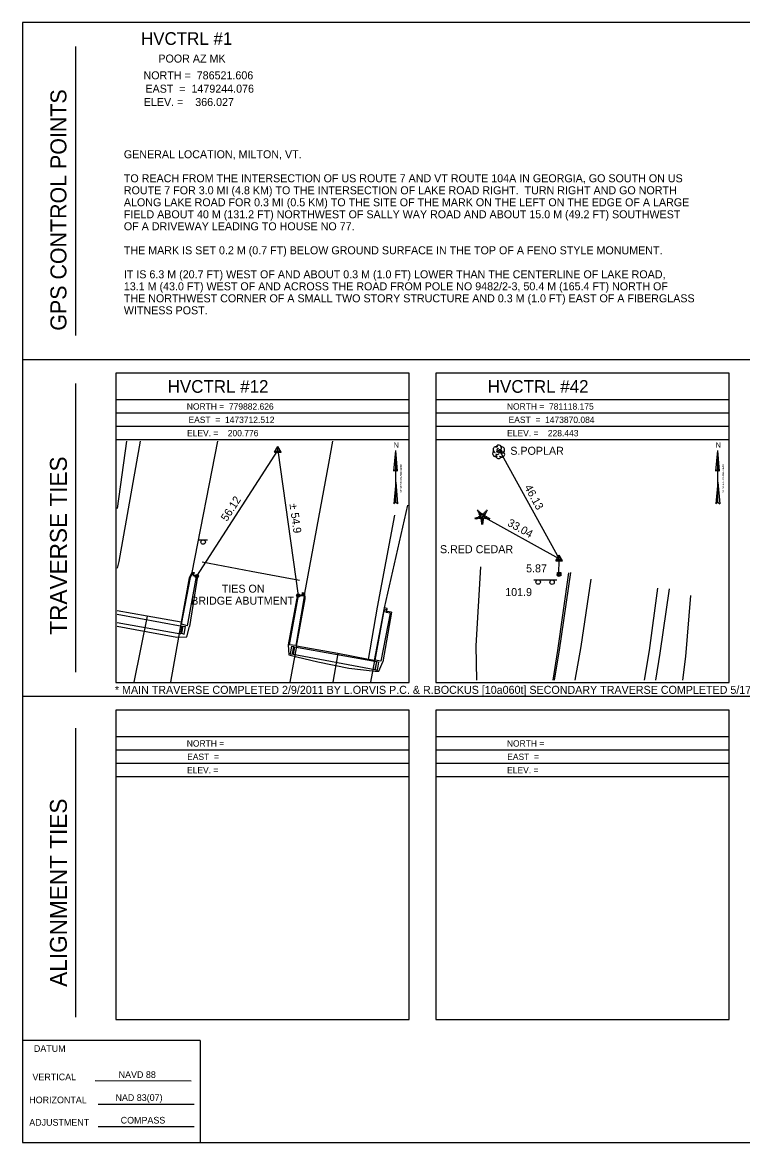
# Model space of a CAD drawing. Extents: x 1472556 to 1473196, y 780590 to 781010.
# Drawn here: x 1472555.8 to 1472825.8, y 780590.3 to 781010.3 of the extents above; entities that cross this region are included whole.
import ezdxf

# ---------------------------------------------------------------- set-up
doc = ezdxf.new("R2010")
doc.units = 0
for name, color, linetype in [('BELB', 7, 'Continuous'), ('BSE', 7, 'Continuous'), ('BSUBM', 7, 'Continuous'), ('CBP', 7, 'Continuous'), ('CPSM', 7, 'Continuous'), ('Default', 7, 'Continuous'), ('L_C', 7, 'Continuous'), ('LABL', 7, 'Continuous'), ('LARO', 7, 'Continuous'), ('LTC', 7, 'Continuous'), ('LTD', 7, 'Continuous'), ('NBL1', 7, 'Continuous'), ('NBL2', 7, 'Continuous'), ('NNA_P', 7, 'Continuous'), ('PET', 7, 'Continuous'), ('PSP', 7, 'Continuous'), ('RGR', 7, 'Continuous'), ('S_C', 7, 'Continuous'), ('SRM', 7, 'Continuous'), ('SSGN', 7, 'Continuous')]:
    doc.layers.add(name, color=color, linetype=linetype)

msp = doc.modelspace()

# ---------------------------------------------------------------- linework, layer by layer
at = {"layer": 'BELB'}
for points in [[(1472602.59, 780787.66), (1472597.5, 780762.96)], [(1472615.29, 780785.38), (1472611.28, 780762.96)], [(1472658.48, 780776.41), (1472656.01, 780762.96)], [(1472674.05, 780773.65), (1472672.15, 780762.96)], [(1472687.79, 780771.06), (1472686.28, 780762.96)]]:
    msp.add_lwpolyline(points, dxfattribs=at)
at = {"layer": 'BSE'}
for points in [[(1472591.36, 780788.41), (1472615.64, 780783.98)], [(1472591.36, 780785.36), (1472615.18, 780781.1), (1472615.64, 780783.98)], [(1472657.83, 780776.23), (1472657.33, 780773.41), (1472687.95, 780767.69)], [(1472657.83, 780776.23), (1472688.47, 780770.65), (1472687.95, 780767.69)]]:
    msp.add_lwpolyline(points, dxfattribs=at)
at = {"layer": 'BSUBM'}
for points in [[(1472617.66, 780784.06), (1472615.44, 780784.62), (1472618.76, 780802.17), (1472619.42, 780803.54), (1472619.92, 780803.51), (1472619.64, 780802.93), (1472621.02, 780802.58)], [(1472617.66, 780784.06), (1472621.02, 780802.58)], [(1472619.27, 780804.11), (1472620.11, 780804), (1472619.87, 780803.06), (1472621.41, 780802.68), (1472618.46, 780783.83)], [(1472658.92, 780795.76), (1472655.41, 780776.94), (1472655.6, 780773.22), (1472658.62, 780772.41), (1472666.5, 780770.53), (1472678.17, 780768.22), (1472688.03, 780767.04), (1472689.44, 780767.08), (1472690.9, 780770.6)], [(1472659.22, 780795.43), (1472661.11, 780795.31), (1472661.1, 780796.13), (1472661.54, 780796.12), (1472661.32, 780794.25), (1472658.24, 780776.71), (1472655.84, 780776.9)], [(1472659.22, 780795.43), (1472655.84, 780776.9)], [(1472658.92, 780795.76), (1472660.63, 780795.52), (1472660.78, 780796.61)], [(1472660.78, 780796.61), (1472661.69, 780796.3)], [(1472693.66, 780788.83), (1472690.19, 780770.82), (1472688.01, 780771.14), (1472691.3, 780789.11), (1472691.76, 780790.3), (1472692.11, 780790.19), (1472692.01, 780789.24), (1472693.67, 780788.9)], [(1472694.19, 780789.21), (1472690.9, 780770.6)], [(1472692.49, 780790.61), (1472691.48, 780790.77)], [(1472694.19, 780789.21), (1472692.42, 780789.48), (1472692.49, 780790.61)], [(1472693.66, 780788.83), (1472693.67, 780788.9)], [(1472591.36, 780783.93), (1472598.02, 780782.63), (1472613.68, 780779.87), (1472617.47, 780779.96), (1472618.46, 780783.83)], [(1472615.97, 780783.94), (1472615.39, 780781.28), (1472616.4, 780780.97), (1472616.88, 780783.77)], [(1472615.97, 780783.94), (1472616.88, 780783.77)], [(1472656.66, 780776.45), (1472656.14, 780773.6), (1472657.02, 780773.41), (1472657.51, 780776.31)], [(1472656.66, 780776.45), (1472657.51, 780776.31)], [(1472688.58, 780770.63), (1472688.08, 780767.67), (1472688.9, 780767.43), (1472689.44, 780770.44)], [(1472688.58, 780770.63), (1472689.44, 780770.44)]]:
    msp.add_lwpolyline(points, dxfattribs=at)
at = {"layer": 'CBP'}
for centre, radius in [((1472734.72, 780849.54), 0.625), ((1472734.72, 780849.54), 0.0833), ((1472728.11, 780825.22), 0.625), ((1472728.11, 780825.22), 0.0833), ((1472621.13, 780802.65), 0.625), ((1472621.13, 780802.65), 0.0833), ((1472756.88, 780803.24), 0.625), ((1472756.88, 780803.24), 0.0833), ((1472659.22, 780795.43), 0.625), ((1472659.22, 780795.43), 0.0833)]:
    msp.add_circle(centre, radius, dxfattribs=at)
at = {"layer": 'CPSM'}
for p, q in [((1472650.31, 780849.11), (1472651.56, 780851.27)), ((1472650.31, 780849.11), (1472651.57, 780849.83)), ((1472650.31, 780849.11), (1472652.81, 780849.11)), ((1472652.81, 780849.11), (1472651.56, 780851.27)), ((1472651.57, 780849.83), (1472651.56, 780851.27)), ((1472651.57, 780849.83), (1472651.57, 780849.83)), ((1472651.57, 780849.83), (1472652.81, 780849.11)), ((1472755.71, 780808.4), (1472756.96, 780810.56)), ((1472758.21, 780808.4), (1472756.96, 780810.56)), ((1472756.96, 780809.12), (1472756.96, 780810.56)), ((1472755.71, 780808.4), (1472756.96, 780809.12)), ((1472755.71, 780808.4), (1472758.21, 780808.4)), ((1472756.96, 780809.12), (1472756.96, 780809.12)), ((1472756.96, 780809.12), (1472758.21, 780808.4))]:
    msp.add_line(p, q, dxfattribs=at)
at = {"layer": 'Default'}
for p, q in [((1472621.13, 780802.65), (1472651.57, 780849.83)), ((1472651.57, 780849.83), (1472659.22, 780795.43)), ((1472734.72, 780849.54), (1472756.96, 780809.12)), ((1472756.96, 780809.12), (1472728.11, 780825.22)), ((1472756.88, 780803.24), (1472756.96, 780809.12))]:
    msp.add_line(p, q, dxfattribs=at)
at = {"layer": 'LABL'}
msp.add_lwpolyline([(1472727.55, 780806.14), (1472725.79, 780776.56), (1472725.97, 780763.69)], dxfattribs=at)
at = {"layer": 'LARO'}
msp.add_lwpolyline([(1472806.23, 780795.45), (1472804.41, 780772.54), (1472803.21, 780763.69)], dxfattribs=at)
at = {"layer": 'LTC'}
for p, q in [((1472726.32, 780827.25), (1472726.68, 780827.51)), ((1472726.53, 780826.79), (1472727.06, 780827.17)), ((1472726.74, 780826.32), (1472727.44, 780826.83)), ((1472726.95, 780825.85), (1472727.83, 780826.49)), ((1472728.61, 780826.45), (1472729.42, 780825.86)), ((1472728.98, 780826.8), (1472729.66, 780826.3)), ((1472729.35, 780827.14), (1472729.9, 780826.74)), ((1472729.72, 780827.49), (1472730.14, 780827.19)), ((1472725.35, 780824.53), (1472725.51, 780824.06)), ((1472725.81, 780824.75), (1472726.02, 780824.1)), ((1472726.26, 780824.96), (1472726.54, 780824.13)), ((1472726.72, 780825.18), (1472727.05, 780824.16)), ((1472727.17, 780825.4), (1472728.19, 780826.13)), ((1472727.17, 780825.4), (1472727.56, 780824.21)), ((1472728.79, 780824.21), (1472727.56, 780824.21)), ((1472728.75, 780823.71), (1472727.61, 780823.71)), ((1472728.67, 780823.21), (1472727.68, 780823.21)), ((1472728.59, 780822.71), (1472727.75, 780822.71)), ((1472728.5, 780822.21), (1472727.83, 780822.21)), ((1472728.19, 780826.13), (1472729.18, 780825.41)), ((1472729.18, 780825.41), (1472728.79, 780824.21)), ((1472729.62, 780825.14), (1472729.28, 780824.1)), ((1472730.07, 780824.89), (1472729.78, 780824)), ((1472730.51, 780824.64), (1472730.27, 780823.91)), ((1472730.95, 780824.39), (1472730.77, 780823.81))]:
    msp.add_line(p, q, dxfattribs=at)
at = {"layer": 'LTD'}
msp.add_line((1472734.31, 780849.36), (1472734.31, 780849.36), dxfattribs=at)
msp.add_line((1472734.31, 780849.36), (1472734.31, 780849.36), dxfattribs=at)
msp.add_arc((1472734.35, 780850.79), 1.05, 335.5272, 180.9563, dxfattribs=at)
for centre, major_axis, ratio, start_param, end_param in [((1472733.22, 780848.65), (0.58, -1.04), 0.959034, 3.141593, 6.283185), ((1472733.51, 780850.03), (1.21, -0.51), 0.895232, 1.570796, 4.712389), ((1472734.31, 780847.86), (0.26, 1.06), 0.942809, 1.570796, 4.712389), ((1472733.85, 780848.61), (-0.625, -0.083), 0.423636, 0, 3.141593), ((1472734.1, 780849.82), (-0.208, -0.792), 0.645439, 3.141593, 6.283185), ((1472734.81, 780849.19), (-0.5, 0.667), 0.989748, 3.141593, 6.283185), ((1472735.31, 780848.53), (-1.09, 0.79), 0.841452, 1.570796, 4.712389), ((1472735.35, 780849.94), (-1.14, -0.48), 0.949671, 1.570796, 4.712389)]:
    msp.add_ellipse(centre, major_axis=major_axis, ratio=ratio, start_param=start_param, end_param=end_param, dxfattribs=at)
at = {"layer": 'NBL1'}
msp.add_lwpolyline([(1472555.78, 780590.3), (1473195.78, 780590.3), (1473195.78, 781010.3), (1472555.78, 781010.3)], close=True, dxfattribs=at)
at = {"layer": 'NBL2'}
for p, q in [((1472575.78, 780892.97), (1472575.78, 781001.3)), ((1472555.78, 780883.97), (1473195.78, 780883.97)), ((1472575.78, 780766.64), (1472575.78, 780874.97)), ((1472700.78, 780868.8), (1472590.78, 780868.8)), ((1472820.78, 780868.8), (1472710.78, 780868.8)), ((1472700.78, 780863.8), (1472590.78, 780863.8)), ((1472820.78, 780863.8), (1472710.78, 780863.8)), ((1472700.78, 780858.8), (1472590.78, 780858.8)), ((1472820.78, 780858.8), (1472710.78, 780858.8)), ((1472700.78, 780853.8), (1472590.78, 780853.8)), ((1472820.78, 780853.8), (1472710.78, 780853.8)), ((1472555.78, 780757.64), (1473195.78, 780757.64)), ((1472575.78, 780637.3), (1472575.78, 780745.64)), ((1472700.78, 780742.47), (1472590.78, 780742.47)), ((1472820.78, 780742.47), (1472710.78, 780742.47)), ((1472700.78, 780737.47), (1472590.78, 780737.47)), ((1472820.78, 780737.47), (1472710.78, 780737.47)), ((1472700.78, 780732.47), (1472590.78, 780732.47)), ((1472820.78, 780732.47), (1472710.78, 780732.47)), ((1472700.78, 780727.47), (1472590.78, 780727.47)), ((1472820.78, 780727.47), (1472710.78, 780727.47)), ((1472622.44, 780628.56), (1472555.78, 780628.56)), ((1472622.44, 780628.56), (1472622.44, 780590.3)), ((1472622.44, 780628.56), (1472622.44, 780590.3)), ((1472583.02, 780613.53), (1472619.02, 780613.5)), ((1472584.13, 780604.76), (1472620.13, 780604.76)), ((1472584.13, 780596.32), (1472620.13, 780596.29))]:
    msp.add_line(p, q, dxfattribs=at)
for points in [[(1472590.78, 780762.8), (1472700.78, 780762.8), (1472700.78, 780878.8), (1472590.78, 780878.8)], [(1472710.78, 780762.8), (1472820.78, 780762.8), (1472820.78, 780878.8), (1472710.78, 780878.8)], [(1472590.78, 780636.47), (1472700.78, 780636.47), (1472700.78, 780752.47), (1472590.78, 780752.47)], [(1472710.78, 780636.47), (1472820.78, 780636.47), (1472820.78, 780752.47), (1472710.78, 780752.47)]]:
    msp.add_lwpolyline(points, close=True, dxfattribs=at)
at = {"layer": 'NNA_P'}
for p, q in [((1472695.02, 780842.02), (1472695.72, 780849.82)), ((1472695.72, 780830.44), (1472695.72, 780849.82)), ((1472696.41, 780842.02), (1472695.72, 780849.82)), ((1472815.78, 780842.02), (1472816.47, 780849.82)), ((1472816.48, 780830.44), (1472816.47, 780849.82)), ((1472817.17, 780842.02), (1472816.47, 780849.82)), ((1472695.02, 780842.02), (1472695.72, 780842.79)), ((1472696.41, 780842.02), (1472695.72, 780842.79)), ((1472815.78, 780842.02), (1472816.48, 780842.79)), ((1472817.17, 780842.02), (1472816.48, 780842.79)), ((1472695.72, 780837.97), (1472695, 780829.8)), ((1472695.72, 780837.97), (1472696.44, 780829.8)), ((1472816.48, 780837.97), (1472815.76, 780829.8)), ((1472816.48, 780837.97), (1472817.2, 780829.8)), ((1472695.72, 780830.44), (1472695, 780829.8)), ((1472695.72, 780830.44), (1472696.44, 780829.8)), ((1472816.48, 780830.44), (1472815.76, 780829.8)), ((1472816.48, 780830.44), (1472817.2, 780829.8))]:
    msp.add_line(p, q, dxfattribs=at)
at = {"layer": 'PET'}
for points in [[(1472628.9, 780853.32), (1472619.27, 780804.11), (1472618.34, 780802.08), (1472615.29, 780785.38), (1472602.59, 780787.66), (1472591.36, 780789.64)], [(1472599.97, 780853.32), (1472591.89, 780808.21), (1472591.36, 780805.69)], [(1472685.53, 780771.44), (1472674.05, 780773.65), (1472658.48, 780776.41), (1472661.73, 780794.17), (1472661.69, 780796.3), (1472670.7, 780844.92), (1472672.17, 780853.32)], [(1472687.79, 780771.06), (1472685.53, 780771.44), (1472688.89, 780791), (1472695.45, 780825.55)], [(1472768.91, 780801.5), (1472765.12, 780776.25), (1472762.92, 780763.69)], [(1472793.82, 780798.2), (1472790.77, 780774.86), (1472788.84, 780763.69)]]:
    msp.add_lwpolyline(points, dxfattribs=at)
at = {"layer": 'PSP'}
for points in [[(1472594.76, 780853.32), (1472591.36, 780828.06)], [(1472687.79, 780771.06), (1472691.48, 780790.77), (1472700.3, 780829.24)], [(1472761.21, 780804.04), (1472757, 780774.97), (1472755.11, 780763.69)], [(1472798.19, 780797.9), (1472794.74, 780773.87), (1472793.14, 780763.69)]]:
    msp.add_lwpolyline(points, dxfattribs=at)
at = {"layer": 'RGR'}
for points in [[(1472623.2, 780808.07), (1472641.56, 780804.59), (1472659.67, 780801.15)], [(1472760.54, 780803.97), (1472756.4, 780774.87), (1472754.58, 780763.69)]]:
    msp.add_lwpolyline(points, dxfattribs=at)
at = {"layer": 'SRM'}
msp.add_lwpolyline([(1472756.33, 780804.02), (1472757.58, 780804.02), (1472757.58, 780802.77), (1472756.33, 780802.77)], close=True, dxfattribs=at)
msp.add_circle((1472756.96, 780803.39), 0.0833, dxfattribs=at)
at = {"layer": 'SSGN'}
for p, q in [((1472621.89, 780816.31), (1472625.22, 780816.31)), ((1472623.53, 780815.47), (1472623.53, 780815.47)), ((1472747.48, 780801.31), (1472756.08, 780801.31)), ((1472751.5, 780800.41), (1472751.5, 780800.41))]:
    msp.add_line(p, q, dxfattribs=at)
for centre in [(1472623.53, 780815.47), (1472749.14, 780800.48), (1472754.36, 780800.41)]:
    msp.add_circle(centre, 0.833, dxfattribs=at)

# ---------------------------------------------------------------- texts
at = {"layer": 'Default'}
for s, p in [('GENERAL LOCATION, MILTON, VT.', (1472593.81, 780959.36)), ('TO REACH FROM THE INTERSECTION OF US ROUTE 7 AND VT ROUTE 104A IN GEORGIA, GO SOUTH ON US ', (1472593.81, 780950.36)), ('ROUTE 7 FOR 3.0 MI (4.8 KM) TO THE INTERSECTION OF LAKE ROAD RIGHT.  TURN RIGHT AND GO NORTH ', (1472593.81, 780945.86)), ('ALONG LAKE ROAD FOR 0.3 MI (0.5 KM) TO THE SITE OF THE MARK ON THE LEFT ON THE EDGE OF A LARGE ', (1472593.81, 780941.36)), ('FIELD ABOUT 40 M (131.2 FT) NORTHWEST OF SALLY WAY ROAD AND ABOUT 15.0 M (49.2 FT) SOUTHWEST ', (1472593.81, 780936.86)), ('OF A DRIVEWAY LEADING TO HOUSE NO 77.', (1472593.81, 780932.36)), ('THE MARK IS SET 0.2 M (0.7 FT) BELOW GROUND SURFACE IN THE TOP OF A FENO STYLE MONUMENT.', (1472593.81, 780923.36)), ('IT IS 6.3 M (20.7 FT) WEST OF AND ABOUT 0.3 M (1.0 FT) LOWER THAN THE CENTERLINE OF LAKE ROAD, ', (1472593.81, 780914.36)), ('13.1 M (43.0 FT) WEST OF AND ACROSS THE ROAD FROM POLE NO 9482/2-3, 50.4 M (165.4 FT) NORTH OF ', (1472593.81, 780909.86)), ('THE NORTHWEST CORNER OF A SMALL TWO STORY STRUCTURE AND 0.3 M (1.0 FT) EAST OF A FIBERGLASS ', (1472593.81, 780905.36)), ('WITNESS POST.', (1472593.81, 780900.86)), ('5.87', (1472744.61, 780804.11)), ('TIES ON', (1472630.51, 780796.49)), ('BRIDGE ABUTMENT', (1472619.05, 780791.99)), ('* MAIN TRAVERSE COMPLETED 2/9/2011 BY L.ORVIS P.C. & R.BOCKUS [10a060t] SECONDARY TRAVERSE COMPLETED 5/17/2011 BY L.ORVIS P.C. & G.HITCHCOCK ', (1472590.46, 780758.56))]:
    msp.add_text(s, height=3, dxfattribs=at).set_placement(p)
for s, rotation, p in [('46.13', 298.8129, (1472743.88, 780836)), ('56.12', 57.1768, (1472632.46, 780822.98)), ('±', 278.0089, (1472655.91, 780829.71)), (' 54.9', 278.0089, (1472656.23, 780827.43)), ('33.04', 330.8256, (1472737.34, 780821.79))]:
    msp.add_text(s, height=3, rotation=rotation, dxfattribs=at).set_placement(p)
at = {"layer": 'L_C'}
for s, p in [('S.POPLAR', (1472738.69, 780848.19)), ('S.RED CEDAR', (1472712.32, 780811.29))]:
    msp.add_text(s, height=3, dxfattribs=at).set_placement(p)
at = {"layer": 'LTC'}
msp.add_text('.', height=1.04, rotation=270, dxfattribs=at).set_placement((1472728.07, 780825.15))
at = {"layer": 'NBL2'}
for s, height, p in [('     HVCTRL #1     ', 4.75, (1472591.41, 781001.88)), ('     POOR AZ MK     ', 3, (1472601.18, 780995.25)), ('NORTH =  786521.606 ', 3, (1472601.18, 780988.96)), ('EAST  =  1479244.076', 3, (1472601.89, 780983.96)), ('ELEV. =    366.027  ', 3, (1472601.29, 780978.96)), ('     HVCTRL #12    ', 4.75, (1472601.42, 780871.43)), ('     HVCTRL #42    ', 4.75, (1472721.42, 780871.43)), ('NORTH =  779882.626 ', 2.375, (1472617.4, 780865.12)), ('NORTH =  781118.175 ', 2.375, (1472737.4, 780865.12)), ('EAST  =  1473712.512', 2.375, (1472618.05, 780860.12)), ('EAST  =  1473870.084', 2.375, (1472738.05, 780860.12)), ('ELEV. =    200.776  ', 2.375, (1472617.5, 780855.12)), ('ELEV. =    228.443  ', 2.375, (1472737.5, 780855.12)), ('NORTH =             ', 2.375, (1472617.4, 780738.78)), ('NORTH =             ', 2.375, (1472737.4, 780738.78)), ('EAST  =             ', 2.375, (1472617.54, 780733.78)), ('EAST  =             ', 2.375, (1472737.54, 780733.78)), ('ELEV. =             ', 2.375, (1472617.5, 780728.78)), ('ELEV. =             ', 2.375, (1472737.5, 780728.78)), ('DATUM', 2.5, (1472560.09, 780624.32)), ('  NAVD 88 ', 2.5, (1472590, 780614.54)), ('NAD 83(07) ', 2.5, (1472590.67, 780605.93)), ('HORIZONTAL', 2.5, (1472558.35, 780605.06)), ('  COMPASS ', 2.5, (1472590.77, 780597.45)), ('ADJUSTMENT', 2.5, (1472558.35, 780596.62))]:
    msp.add_text(s, height=height, dxfattribs=at).set_placement(p)
for s, height, rotation, p in [('GPS CONTROL POINTS', 6, 90, (1472572.28, 780894.72)), ('TRAVERSE TIES', 6.3332, 90, (1472572.44, 780780.74)), ('ALIGNMENT TIES', 6.3332, 90, (1472572.44, 780648.71)), ('VERTICAL', 2.5, 0.1439, (1472559.55, 780613.65))]:
    msp.add_text(s, height=height, rotation=rotation, dxfattribs=at).set_placement(p)
at = {"layer": 'NNA_P'}
for p in [(1472694.95, 780850.83), (1472815.71, 780850.83)]:
    msp.add_text('N', height=1.97, dxfattribs=at).set_placement(p)
for p in [(1472698.07, 780834), (1472818.83, 780834)]:
    msp.add_text('VT STATE PLANE GRID', height=0.7, rotation=90.0204, dxfattribs=at).set_placement(p)
at = {"layer": 'S_C'}
msp.add_text('101.9', height=3, dxfattribs=at).set_placement((1472736.78, 780795.22))

doc.saveas('drawing.dxf')
